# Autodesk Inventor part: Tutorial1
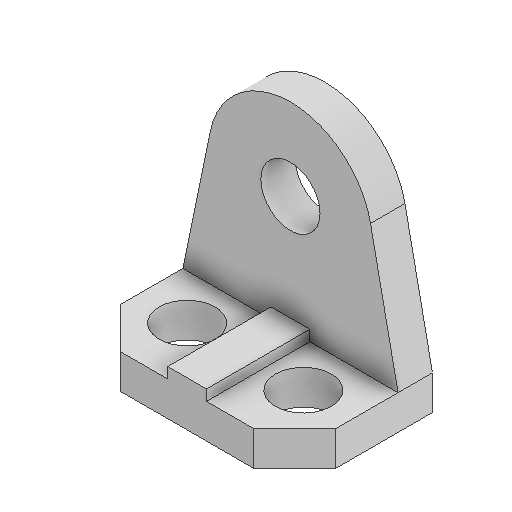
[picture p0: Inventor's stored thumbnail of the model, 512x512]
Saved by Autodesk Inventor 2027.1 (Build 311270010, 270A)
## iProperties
Created: 2021-03
Part Number: Tutorial1
Material: Generic
Document SubType Name: Modeling
Designer: ASUS Laptop
Density: 1 g/cm^3
Appearance: Default
Author: ASUS Laptop
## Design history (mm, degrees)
sketch "Sketch1"
  geometry: L1 (0, 0)-(-200, 0); L2 (-200, 0)-(-200, 90); L3 (-200, 90)-(-162, 128); L4 (-162, 128)-(-38, 128); L5 (-38, 128)-(0, 90); L6 (0, 90)-(0, 0); L7 (-154, 74)-(-31.817, 74); C1 r 26 at (-154, 74); C2 r 26 at (-46, 74); 1 further point
  constraints: 14 end point, 2 centre point, 2 horizontal, 2 parallel, 2 perpendicular, 1 coincident, 1 equal radius, 1 point on line
  dimensions: "d0" = 128 distance between parallel lines of L4 L1; "d1" = 90 distance of L1.end L2.end; "d2" = 124 distance of L3.end L4.end; "d3" = 38 horizontal distance of L3.end L2.end; "d4" = 38 horizontal distance of L5.end L4.end; "d5" = 46 distance from line of L7.start L2; "d6" = 46 distance from line of L6 C2.centre; "d7" = 74 distance from line of L7.start L1; "d8" = 52 diameter of C2
extrude "Extrusion1" new body sketch "Sketch1" distance "d9" = 32; taper "d10" = 0 deg
sketch "Sketch2"
  geometry: L1 (200, 32)-(162, 32) reference; L2 (200, 32)-(174.418, 155.424); L3 (38, 32)-(0, 32) reference; L4 (25.582, 155.424)-(0, 32); L5 (0, 32)-(200, 32); L6 (162, 0)-(38, 0) reference; L7 (100, 0)-(100, 176.194); C1 r 27.5 at (100, 140); A1 r 76 centre (100, 140) between (174.418, 155.424) and (25.582, 155.424); 3 further points
  constraints: 8 end point, 2 centre point, 2 point on circle, 2 tangent, 1 coincident, 1 collinear, 1 midpoint, 1 vertical, 1 other
  dimensions: "d11" = 76 radius of A1; "d12" = 108 distance from line of A1.centre L5; "d13" = 55 diameter of C1
extrude "Extrusion2" join sketch "Sketch2" distance "d14" = 32; taper "d15" = 0 deg
sketch "Sketch4"
  geometry: L1 (0, 32)-(124, 32) reference; L2 (44, 32)-(80, 32); L3 (80, 32)-(80, 42); L4 (80, 42)-(44, 42); L5 (44, 42)-(44, 32); L6 (-38, 0)-(-38, 32) reference; 1 further point
  constraints: 8 end point, 2 parallel, 1 horizontal, 1 perpendicular, 1 point on line
  dimensions: "d16" = 36 distance of L3.end L4.end; "d17" = 10 distance of L4.end L2.start; "d18" = 82 distance between parallel lines of L5 L6
extrude "Extrusion3" join sketch "Sketch4" stored distance "d19" = 32; taper "d20" = 0 deg
body "Solid1"
sketch "Sketch3"
  geometry: 1 further point
